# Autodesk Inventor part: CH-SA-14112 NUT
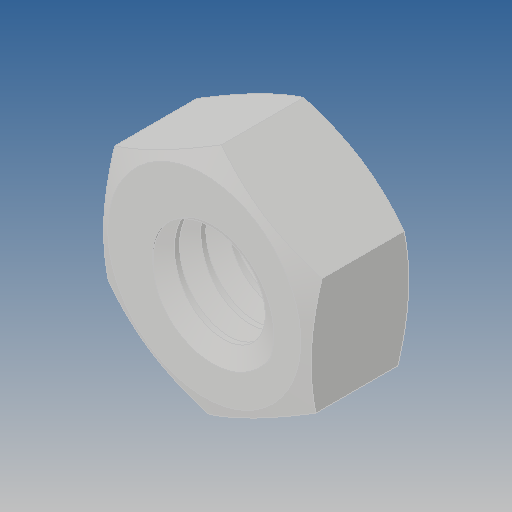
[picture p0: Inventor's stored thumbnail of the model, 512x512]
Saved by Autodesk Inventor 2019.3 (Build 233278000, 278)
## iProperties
Created: 2017-12
Part Number: CH-SA-14112 NUT
Material: Ogólny
Document SubType Name: Modeling
Designer: Admin
Density: 1 g/cm^3
Appearance: Domyślna
Author: Admin
Revision Number: ÈÎºÎ
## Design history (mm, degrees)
feature "¾µÏò1"
node "Bryła1"
